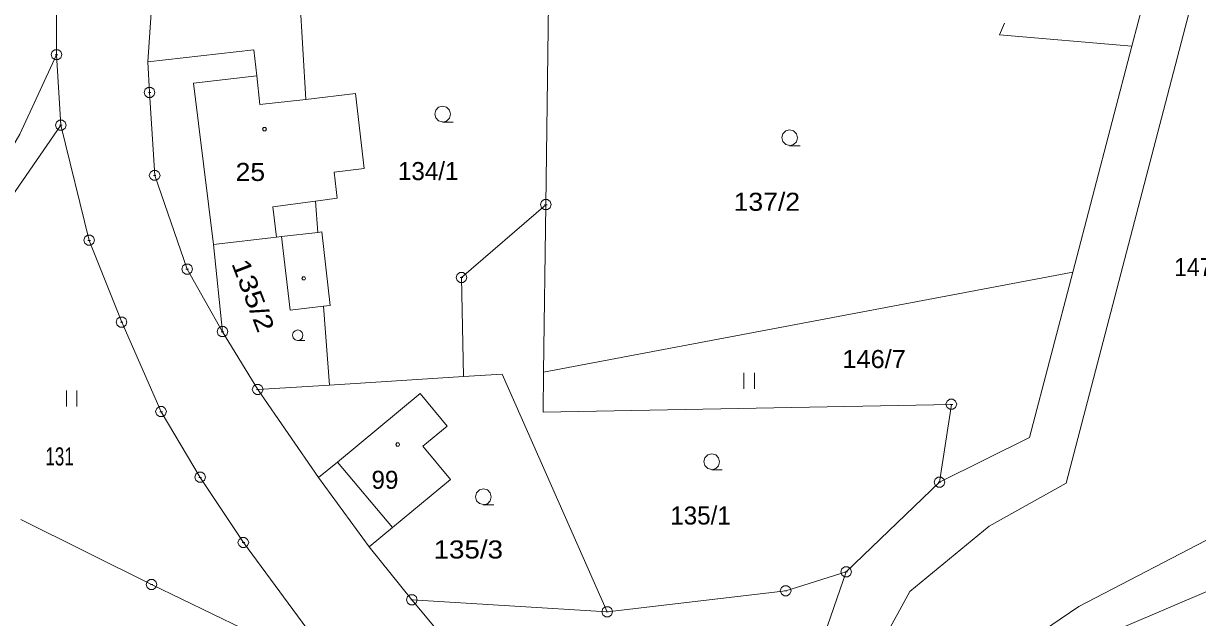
# Model space of a CAD drawing. Extents: x -687390 to -684106, y -954833 to -951648.
# Drawn here: x -686969.4 to -686858.8, y -952583.1 to -952527.1 of the extents above; entities that cross this region are included whole.
import ezdxf

# ---------------------------------------------------------------- set-up
doc = ezdxf.new("R2010")
doc.units = 0
doc.header["$LTSCALE"] = 0.68
for name, color, linetype, lineweight in [('1', 7, 'Continuous', 13), ('3', 7, 'Continuous', 13), ('4', 7, 'Continuous', 13), ('5', 7, 'Continuous', 13), ('8', 7, 'Continuous', 13)]:
    doc.layers.add(name, color=color, linetype=linetype, lineweight=lineweight)
doc.layers.add('2', color=7, linetype='Continuous')

msp = doc.modelspace()

# ---------------------------------------------------------------- linework, layer by layer
at = {"layer": '1'}
for p, q in [((-686865.02, -952529.26), (-686843.91, -952448.54)), ((-686853.14, -952501.21), (-686871.22, -952570.41)), ((-686957.24, -952524.25), (-686957.66, -952530.75)), ((-686943.39, -952524.05), (-686942.8, -952534.28)), ((-686920.19, -952544.2), (-686919.93, -952525.23)), ((-686877.48, -952528.2), (-686877.01, -952527.1)), ((-686877.48, -952528.2), (-686865.02, -952529.26)), ((-686870.58, -952550.53), (-686865.02, -952529.26)), ((-686966.27, -952530.08), (-686965.86, -952536.72)), ((-686957.66, -952530.75), (-686957.5, -952533.63)), ((-686957.02, -952541.44), (-686957.5, -952533.63)), ((-686965.86, -952536.72), (-686971.98, -952545.58)), ((-686963.19, -952547.55), (-686965.86, -952536.72)), ((-686953.97, -952550.26), (-686957.02, -952541.44)), ((-686941.88, -952543.85), (-686939.83, -952543.57)), ((-686941.66, -952546.8), (-686941.88, -952543.85)), ((-686928.14, -952551.05), (-686920.19, -952544.2)), ((-686920.41, -952559.96), (-686920.19, -952544.2)), ((-686951.47, -952547.94), (-686945.55, -952547.25)), ((-686945.55, -952547.25), (-686945.08, -952547.2)), ((-686941.66, -952546.8), (-686941.3, -952546.76)), ((-686940.5, -952553.68), (-686941.3, -952546.76)), ((-686951.47, -952547.94), (-686950.64, -952556.15)), ((-686950.64, -952556.15), (-686953.97, -952550.26)), ((-686920.41, -952559.96), (-686870.58, -952550.53)), ((-686874.67, -952566.12), (-686870.58, -952550.53)), ((-686927.94, -952560.38), (-686928.14, -952551.05)), ((-686941.12, -952553.76), (-686940.5, -952553.68)), ((-686940.55, -952561.17), (-686941.12, -952553.76)), ((-686947.32, -952561.59), (-686950.64, -952556.15)), ((-686927.94, -952560.38), (-686940.55, -952561.17)), ((-686924.31, -952560.15), (-686927.94, -952560.38)), ((-686920.46, -952563.73), (-686920.41, -952559.96)), ((-686940.55, -952561.17), (-686947.32, -952561.59)), ((-686947.32, -952561.59), (-686941.59, -952569.88)), ((-686874.67, -952566.12), (-686883.13, -952570.32)), ((-686939.82, -952568.42), (-686941.59, -952569.88)), ((-686941.59, -952569.88), (-686936.83, -952576.4)), ((-686891.91, -952578.77), (-686883.13, -952570.32)), ((-686871.22, -952570.41), (-686878.45, -952574.45)), ((-686957.31, -952579.96), (-686969.61, -952573.84)), ((-686934.64, -952574.57), (-686936.83, -952576.4)), ((-686936.83, -952576.4), (-686932.8, -952581.39)), ((-686891.91, -952578.77), (-686894.97, -952587.49)), ((-686939.36, -952588.6), (-686957.31, -952579.96))]:
    msp.add_line(p, q, dxfattribs=at)
for points in [[(-687002.39, -952541.61), (-686984.71, -952559.53), (-686977.54, -952551.02), (-686969.71, -952537.55), (-686966.27, -952530.08), (-686966.24, -952522.04), (-686964.21, -952515.71)], [(-686939.83, -952543.57), (-686940.12, -952541.12), (-686937.29, -952540.8), (-686938.1, -952533.74), (-686942.8, -952534.28)], [(-686841.76, -952549.24), (-686854.34, -952579.07), (-686866.94, -952584.44), (-686875.59, -952592.39), (-686879.48, -952588.46), (-686870, -952582.01), (-686856.5, -952574.99), (-686842.04, -952539.83)], [(-686939.36, -952588.6), (-686948.67, -952576), (-686952.74, -952569.86), (-686956.42, -952563.68), (-686960.13, -952555.25), (-686963.19, -952547.55)], [(-686945.08, -952547.2), (-686944.26, -952554.13), (-686941.12, -952553.76)], [(-686924.31, -952560.15), (-686914.41, -952582.52), (-686932.8, -952581.39)], [(-686939.82, -952568.42), (-686932.03, -952561.97), (-686929.48, -952565.05), (-686931.76, -952566.93), (-686929.18, -952570.06), (-686934.64, -952574.57)], [(-686883.13, -952570.32), (-686882.01, -952562.99), (-686920.46, -952563.73)], [(-686897.63, -952602.05), (-686885.92, -952580.62), (-686878.45, -952574.45)], [(-686914.41, -952582.52), (-686897.61, -952580.54), (-686891.91, -952578.77)], [(-686932.8, -952581.39), (-686915.2, -952602.5), (-686911.95, -952609.93)]]:
    msp.add_lwpolyline(points, dxfattribs=at)
at = {"layer": '3'}
for p, q in [((-686901.55, -952560.02), (-686901.55, -952561.52)), ((-686900.55, -952561.52), (-686900.55, -952560.02)), ((-686965.34, -952561.7), (-686965.34, -952563.2)), ((-686964.34, -952563.2), (-686964.34, -952561.7))]:
    msp.add_line(p, q, dxfattribs=at)
for points in [[(-686929.91, -952536.4), (-686930.29, -952536.3), (-686930.56, -952536.03), (-686930.66, -952535.66), (-686930.56, -952535.29), (-686930.29, -952535.02), (-686929.92, -952534.92), (-686929.55, -952535.02), (-686929.28, -952535.29), (-686929.18, -952535.67), (-686929.28, -952536.05), (-686929.55, -952536.32), (-686929.93, -952536.42), (-686928.93, -952536.42)], [(-686897.23, -952538.62), (-686897.61, -952538.52), (-686897.88, -952538.25), (-686897.98, -952537.88), (-686897.88, -952537.51), (-686897.61, -952537.24), (-686897.24, -952537.14), (-686896.87, -952537.24), (-686896.6, -952537.51), (-686896.5, -952537.89), (-686896.6, -952538.27), (-686896.87, -952538.54), (-686897.25, -952538.64), (-686896.25, -952538.64)], [(-686943.55, -952556.98), (-686943.805, -952556.913), (-686943.986, -952556.732), (-686944.052, -952556.484), (-686943.986, -952556.236), (-686943.805, -952556.055), (-686943.557, -952555.988), (-686943.309, -952556.055), (-686943.128, -952556.236), (-686943.061, -952556.491), (-686943.128, -952556.746), (-686943.309, -952556.926), (-686943.563, -952556.993), (-686942.893, -952556.993)], [(-686904.56, -952569.12), (-686904.94, -952569.02), (-686905.21, -952568.75), (-686905.31, -952568.38), (-686905.21, -952568.01), (-686904.94, -952567.74), (-686904.57, -952567.64), (-686904.2, -952567.74), (-686903.93, -952568.01), (-686903.83, -952568.39), (-686903.93, -952568.77), (-686904.2, -952569.04), (-686904.58, -952569.14), (-686903.58, -952569.14)], [(-686926.06, -952572.43), (-686926.44, -952572.33), (-686926.71, -952572.06), (-686926.81, -952571.69), (-686926.71, -952571.32), (-686926.44, -952571.05), (-686926.07, -952570.95), (-686925.7, -952571.05), (-686925.43, -952571.32), (-686925.33, -952571.7), (-686925.43, -952572.08), (-686925.7, -952572.35), (-686926.08, -952572.45), (-686925.08, -952572.45)]]:
    msp.add_lwpolyline(points, dxfattribs=at)
at = {"layer": '4'}
for p, q in [((-686947.13, -952534.77), (-686947.41, -952532.07)), ((-686942.8, -952534.28), (-686947.13, -952534.77)), ((-686945.08, -952547.2), (-686941.66, -952546.8)), ((-686939.82, -952568.42), (-686934.64, -952574.57))]:
    msp.add_line(p, q, dxfattribs=at)
for points in [[(-686957.66, -952530.75), (-686947.68, -952529.62), (-686947.41, -952532.07)], [(-686947.41, -952532.07), (-686953.37, -952532.75), (-686951.47, -952547.94)], [(-686945.55, -952547.25), (-686945.89, -952544.38), (-686941.88, -952543.85)]]:
    msp.add_lwpolyline(points, dxfattribs=at)
at = {"layer": '5'}
for points in [[(-686946.6, -952536.93), (-686946.51, -952537.08), (-686946.6, -952537.23), (-686946.78, -952537.23), (-686946.87, -952537.08), (-686946.78, -952536.93)], [(-686942.9, -952550.98), (-686942.81, -952551.13), (-686942.9, -952551.28), (-686943.08, -952551.28), (-686943.17, -952551.13), (-686943.08, -952550.98)], [(-686934.05, -952566.61), (-686933.96, -952566.76), (-686934.05, -952566.91), (-686934.23, -952566.91), (-686934.32, -952566.76), (-686934.23, -952566.61)]]:
    msp.add_lwpolyline(points, close=True, dxfattribs=at)
at = {"layer": '8'}
for p, q in [((-686966.39, -952530.08), (-686966.15, -952530.08)), ((-686957.62, -952533.63), (-686957.38, -952533.63)), ((-686965.98, -952536.72), (-686965.74, -952536.72)), ((-686957.14, -952541.44), (-686956.9, -952541.44)), ((-686920.31, -952544.2), (-686920.07, -952544.2)), ((-686963.31, -952547.55), (-686963.07, -952547.55)), ((-686954.09, -952550.26), (-686953.85, -952550.26)), ((-686928.26, -952551.05), (-686928.02, -952551.05)), ((-686960.25, -952555.25), (-686960.01, -952555.25)), ((-686950.76, -952556.15), (-686950.52, -952556.15)), ((-686947.44, -952561.59), (-686947.2, -952561.59)), ((-686882.13, -952562.99), (-686881.89, -952562.99)), ((-686956.54, -952563.68), (-686956.3, -952563.68)), ((-686952.86, -952569.86), (-686952.62, -952569.86)), ((-686883.25, -952570.32), (-686883.01, -952570.32)), ((-686948.79, -952576), (-686948.55, -952576)), ((-686892.03, -952578.77), (-686891.79, -952578.77)), ((-686957.43, -952579.96), (-686957.19, -952579.96)), ((-686897.73, -952580.54), (-686897.49, -952580.54)), ((-686932.92, -952581.39), (-686932.68, -952581.39)), ((-686914.53, -952582.52), (-686914.29, -952582.52))]:
    msp.add_line(p, q, dxfattribs=at)
for points in [[(-686966.12, -952529.6), (-686965.87, -952529.78), (-686965.77, -952530.07), (-686965.87, -952530.36), (-686966.12, -952530.54), (-686966.43, -952530.54), (-686966.68, -952530.36), (-686966.78, -952530.07), (-686966.68, -952529.78), (-686966.43, -952529.6)], [(-686957.35, -952533.15), (-686957.1, -952533.33), (-686957, -952533.62), (-686957.1, -952533.91), (-686957.35, -952534.09), (-686957.66, -952534.09), (-686957.91, -952533.91), (-686958.01, -952533.62), (-686957.91, -952533.33), (-686957.66, -952533.15)], [(-686965.71, -952536.24), (-686965.46, -952536.42), (-686965.36, -952536.71), (-686965.46, -952537), (-686965.71, -952537.18), (-686966.02, -952537.18), (-686966.27, -952537), (-686966.37, -952536.71), (-686966.27, -952536.42), (-686966.02, -952536.24)], [(-686956.87, -952540.96), (-686956.62, -952541.14), (-686956.52, -952541.43), (-686956.62, -952541.72), (-686956.87, -952541.9), (-686957.18, -952541.9), (-686957.43, -952541.72), (-686957.53, -952541.43), (-686957.43, -952541.14), (-686957.18, -952540.96)], [(-686920.04, -952543.72), (-686919.79, -952543.9), (-686919.69, -952544.19), (-686919.79, -952544.48), (-686920.04, -952544.66), (-686920.35, -952544.66), (-686920.6, -952544.48), (-686920.7, -952544.19), (-686920.6, -952543.9), (-686920.35, -952543.72)], [(-686963.04, -952547.07), (-686962.79, -952547.25), (-686962.69, -952547.54), (-686962.79, -952547.83), (-686963.04, -952548.01), (-686963.35, -952548.01), (-686963.6, -952547.83), (-686963.7, -952547.54), (-686963.6, -952547.25), (-686963.35, -952547.07)], [(-686953.82, -952549.78), (-686953.57, -952549.96), (-686953.47, -952550.25), (-686953.57, -952550.54), (-686953.82, -952550.72), (-686954.13, -952550.72), (-686954.38, -952550.54), (-686954.48, -952550.25), (-686954.38, -952549.96), (-686954.13, -952549.78)], [(-686927.99, -952550.57), (-686927.74, -952550.75), (-686927.64, -952551.04), (-686927.74, -952551.33), (-686927.99, -952551.51), (-686928.3, -952551.51), (-686928.55, -952551.33), (-686928.65, -952551.04), (-686928.55, -952550.75), (-686928.3, -952550.57)], [(-686959.98, -952554.77), (-686959.73, -952554.95), (-686959.63, -952555.24), (-686959.73, -952555.53), (-686959.98, -952555.71), (-686960.29, -952555.71), (-686960.54, -952555.53), (-686960.64, -952555.24), (-686960.54, -952554.95), (-686960.29, -952554.77)], [(-686950.49, -952555.67), (-686950.24, -952555.85), (-686950.14, -952556.14), (-686950.24, -952556.43), (-686950.49, -952556.61), (-686950.8, -952556.61), (-686951.05, -952556.43), (-686951.15, -952556.14), (-686951.05, -952555.85), (-686950.8, -952555.67)], [(-686947.17, -952561.11), (-686946.92, -952561.29), (-686946.82, -952561.58), (-686946.92, -952561.87), (-686947.17, -952562.05), (-686947.48, -952562.05), (-686947.73, -952561.87), (-686947.83, -952561.58), (-686947.73, -952561.29), (-686947.48, -952561.11)], [(-686956.27, -952563.2), (-686956.02, -952563.38), (-686955.92, -952563.67), (-686956.02, -952563.96), (-686956.27, -952564.14), (-686956.58, -952564.14), (-686956.83, -952563.96), (-686956.93, -952563.67), (-686956.83, -952563.38), (-686956.58, -952563.2)], [(-686881.86, -952562.51), (-686881.61, -952562.69), (-686881.51, -952562.98), (-686881.61, -952563.27), (-686881.86, -952563.45), (-686882.17, -952563.45), (-686882.42, -952563.27), (-686882.52, -952562.98), (-686882.42, -952562.69), (-686882.17, -952562.51)], [(-686952.59, -952569.38), (-686952.34, -952569.56), (-686952.24, -952569.85), (-686952.34, -952570.14), (-686952.59, -952570.32), (-686952.9, -952570.32), (-686953.15, -952570.14), (-686953.25, -952569.85), (-686953.15, -952569.56), (-686952.9, -952569.38)], [(-686882.98, -952569.84), (-686882.73, -952570.02), (-686882.63, -952570.31), (-686882.73, -952570.6), (-686882.98, -952570.78), (-686883.29, -952570.78), (-686883.54, -952570.6), (-686883.64, -952570.31), (-686883.54, -952570.02), (-686883.29, -952569.84)], [(-686948.52, -952575.52), (-686948.27, -952575.7), (-686948.17, -952575.99), (-686948.27, -952576.28), (-686948.52, -952576.46), (-686948.83, -952576.46), (-686949.08, -952576.28), (-686949.18, -952575.99), (-686949.08, -952575.7), (-686948.83, -952575.52)], [(-686891.76, -952578.29), (-686891.51, -952578.47), (-686891.41, -952578.76), (-686891.51, -952579.05), (-686891.76, -952579.23), (-686892.07, -952579.23), (-686892.32, -952579.05), (-686892.42, -952578.76), (-686892.32, -952578.47), (-686892.07, -952578.29)], [(-686957.16, -952579.48), (-686956.91, -952579.66), (-686956.81, -952579.95), (-686956.91, -952580.24), (-686957.16, -952580.42), (-686957.47, -952580.42), (-686957.72, -952580.24), (-686957.82, -952579.95), (-686957.72, -952579.66), (-686957.47, -952579.48)], [(-686897.46, -952580.06), (-686897.21, -952580.24), (-686897.11, -952580.53), (-686897.21, -952580.82), (-686897.46, -952581), (-686897.77, -952581), (-686898.02, -952580.82), (-686898.12, -952580.53), (-686898.02, -952580.24), (-686897.77, -952580.06)], [(-686932.65, -952580.91), (-686932.4, -952581.09), (-686932.3, -952581.38), (-686932.4, -952581.67), (-686932.65, -952581.85), (-686932.96, -952581.85), (-686933.21, -952581.67), (-686933.31, -952581.38), (-686933.21, -952581.09), (-686932.96, -952580.91)], [(-686914.26, -952582.04), (-686914.01, -952582.22), (-686913.91, -952582.51), (-686914.01, -952582.8), (-686914.26, -952582.98), (-686914.57, -952582.98), (-686914.82, -952582.8), (-686914.92, -952582.51), (-686914.82, -952582.22), (-686914.57, -952582.04)]]:
    msp.add_lwpolyline(points, close=True, dxfattribs=at)

# ---------------------------------------------------------------- texts
at = {"layer": '2'}
for s, width, p in [('25', 1.1, (-686949.405, -952541.96)), ('137/2', 1.1, (-686902.515, -952544.77)), ('147/1', 0.95, (-686861.035, -952550.92)), ('146/7', 1.05, (-686892.275, -952559.57)), ('131', 0.7, (-686967.305, -952568.74)), ('135/3', 1.15, (-686930.765, -952577.5))]:
    msp.add_text(s, height=1.7, dxfattribs=dict(at, width=width)).set_placement(p)
for s, p in [('134/1', (-686934.115, -952541.88)), ('99', (-686936.605, -952570.94)), ('135/1', (-686908.475, -952574.3))]:
    msp.add_text(s, height=1.7, dxfattribs=at).set_placement(p)
at = {"layer": '2', "width": 1.25}
msp.add_text('135/2', height=1.7, rotation=290.948, dxfattribs=at).set_placement((-686949.819, -952549.723))

doc.saveas('drawing.dxf')
